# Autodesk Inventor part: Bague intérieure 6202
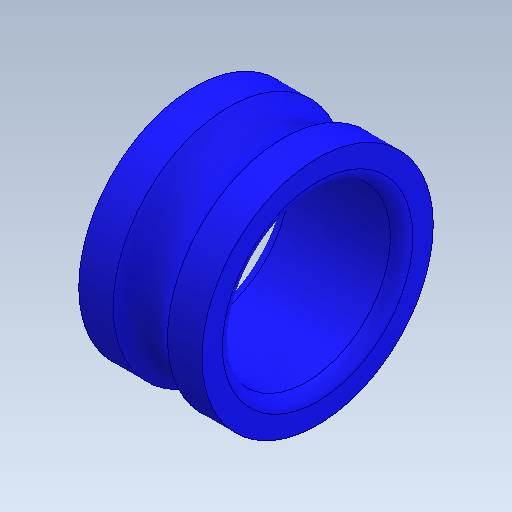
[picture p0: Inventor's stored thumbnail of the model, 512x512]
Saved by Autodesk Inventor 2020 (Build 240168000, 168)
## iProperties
Created: 2003-06
Part Number: Bague intérieure 6202
Material: Générique
Document SubType Name: Modeling
Designer: Bruno
Density: 1 g/cm^3
Appearance: Par défaut
Author: Bruno
Sending System: SolidWorks 2011
Last Author: frederic
Last Saved: 2012-02-20
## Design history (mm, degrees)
feature "Base-Révolution"
node "Solide1"
